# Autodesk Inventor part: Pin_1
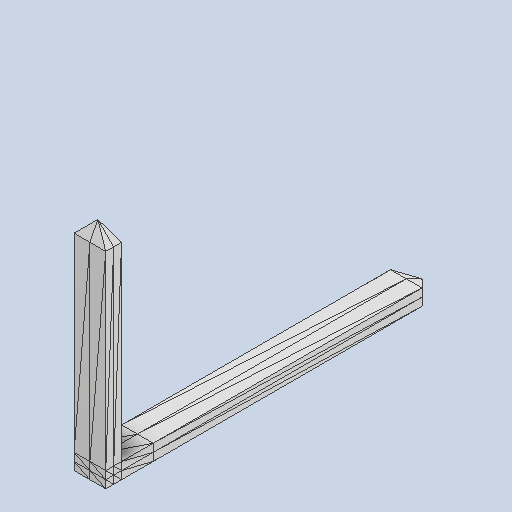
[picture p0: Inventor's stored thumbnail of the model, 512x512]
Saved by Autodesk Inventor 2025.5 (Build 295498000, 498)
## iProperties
Created: 2026-10
Part Number: Pin_1
Material: Genérico
Document SubType Name: Modeling
Designer: Luis M
Density: 1 g/cm^3
Appearance: Valor por defecto
Author: Luis M
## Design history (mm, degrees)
feature "Base1"
node "Sólido1"
